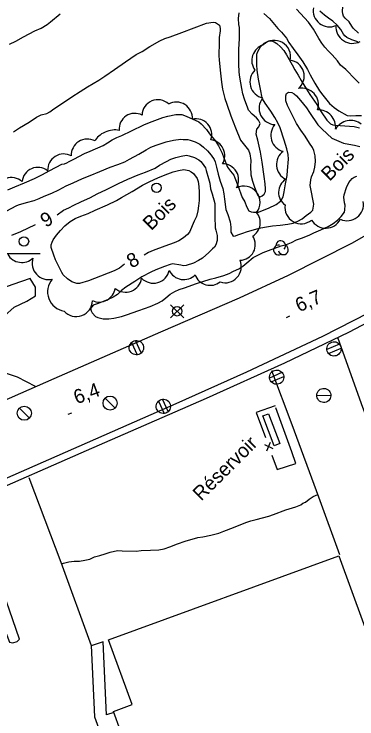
# Model space of a CAD drawing. Extents: x 381879 to 384696, y 5564785 to 5567594.
# Drawn here: x 384004.5 to 384077.4, y 5566301.1 to 5566450.9 of the extents above; entities that cross this region are included whole.
import ezdxf

# ---------------------------------------------------------------- set-up
doc = ezdxf.new("R2010")
doc.units = 0
for name, color, linetype in [('Niveau 19', 7, 'Continuous'), ('Niveau 2', 7, 'Continuous'), ('Niveau 21', 7, 'Continuous'), ('Niveau 22', 7, 'Continuous'), ('Niveau 3', 7, 'Continuous'), ('Niveau 31', 7, 'Continuous'), ('Niveau 33', 7, 'Continuous'), ('Niveau 36', 7, 'Continuous'), ('Niveau 37', 7, 'Continuous'), ('Niveau 4', 7, 'Continuous'), ('Niveau 44', 7, 'Continuous'), ('Niveau 52', 7, 'Continuous'), ('Niveau 61', 7, 'Continuous')]:
    doc.layers.add(name, color=color, linetype=linetype)

msp = doc.modelspace()

# ---------------------------------------------------------------- linework, layer by layer
at = {"layer": 'Niveau 19'}
msp.add_lwpolyline([(384009.04, 5566371.75), (384005.19, 5566373.71), (384000.87, 5566375.14), (383999.42, 5566377.48), (384000.4, 5566382.81), (384002.46, 5566386.78), (384004.5, 5566388.63), (384007.19, 5566389.9), (384009.07, 5566391.03), (384009.06, 5566392.88), (384007.91, 5566394.71), (384004.22, 5566393.43), (383997.83, 5566391.16), (383992.57, 5566388.92), (383990.33, 5566394.2), (383987.67, 5566392.42), (383990.65, 5566385.45), (383993.25, 5566376.84), (383995.32, 5566369.47), (383995.77, 5566367.6)], dxfattribs=at)
at = {"layer": 'Niveau 2'}
for points in [[(384077.69, 5566446.87), (384076.55, 5566447.9), (384076.29, 5566448.38), (384075.68, 5566449.28), (384074.86, 5566450.08), (384074.51, 5566450.51), (384074.33, 5566450.98), (384074.3, 5566451.49), (384074.35, 5566452.56), (384074.66, 5566453.64), (384075.1, 5566454.62), (384076.05, 5566456.52)], [(384077.87, 5566444.81), (384077.34, 5566445.08), (384076.25, 5566445.46), (384075.2, 5566445.94), (384074.8, 5566446.28), (384074.49, 5566446.68), (384073.92, 5566447.65), (384073.14, 5566448.55), (384072.25, 5566449.42), (384071.34, 5566450.05), (384070.44, 5566450.71), (384069.46, 5566451.52)], [(384003.17, 5566413.56), (384004.64, 5566414.2), (384006.7, 5566415.05), (384008.8, 5566415.96), (384010.4, 5566416.78), (384012.08, 5566417.71), (384014.67, 5566419.01), (384015.18, 5566419.09), (384015.67, 5566419.27), (384016.2, 5566419.61), (384017.21, 5566420.12), (384019.45, 5566421.26), (384020.67, 5566421.79), (384023.4, 5566423), (384024.37, 5566423.53), (384025.36, 5566424.16), (384026.33, 5566424.68), (384027.37, 5566425.14), (384029.45, 5566426.12), (384032.1, 5566427.41), (384033.28, 5566427.88), (384036.12, 5566428.95), (384037.19, 5566429.24), (384038.87, 5566429.57), (384040.11, 5566429.56), (384040.71, 5566429.4), (384041.73, 5566428.97), (384043.79, 5566428.01), (384044.24, 5566427.57), (384045.36, 5566426.4), (384046.04, 5566425.5), (384047.39, 5566423.82), (384047.93, 5566422.89), (384048.69, 5566421.34), (384049.05, 5566420.35), (384049.86, 5566418.41), (384050.5, 5566417.52), (384051.2, 5566416.71), (384051.43, 5566416.15), (384052.03, 5566414.51), (384052.96, 5566411.94), (384053.5, 5566410.99), (384053.91, 5566410.01), (384054.4, 5566409.1), (384054.87, 5566408.91), (384055.39, 5566408.84), (384056.41, 5566408.8), (384056.96, 5566409), (384058.54, 5566409.66), (384060.2, 5566410.47), (384061.12, 5566411.15), (384061.43, 5566411.56), (384061.67, 5566412.1), (384061.89, 5566413.15), (384062.2, 5566414.87), (384062.56, 5566416.59), (384062.62, 5566417.67), (384062.82, 5566420.05), (384062.75, 5566421.09), (384062.48, 5566422.25), (384061.91, 5566424.1), (384061.04, 5566426.75), (384060.54, 5566427.84), (384059.93, 5566428.97), (384059.09, 5566430.27), (384057.84, 5566431.97), (384057.29, 5566432.9), (384057.12, 5566433.47), (384056.92, 5566434.62), (384056.43, 5566437.12), (384056.18, 5566439), (384056.11, 5566440.14), (384056.11, 5566442.38), (384056.3, 5566442.94), (384056.83, 5566443.93), (384057.61, 5566444.71), (384058.65, 5566445.25), (384059.23, 5566445.21), (384059.77, 5566445.04)], [(384059.77, 5566445.04), (384060.31, 5566444.67), (384061.14, 5566443.98), (384061.85, 5566443.19), (384062.38, 5566442.23), (384063.6, 5566440.17), (384064.19, 5566439.04), (384064.87, 5566437.96), (384065.52, 5566436.79), (384066.61, 5566434.97), (384067.38, 5566433.84), (384068.82, 5566431.69), (384069.74, 5566430.15), (384070.93, 5566428.4), (384071.74, 5566427.6), (384072.22, 5566427.37), (384072.78, 5566427.28), (384073.81, 5566427.23), (384076.78, 5566427), (384077.88, 5566426.77)], [(384068.01, 5566409.24), (384068.2, 5566410.54), (384068.08, 5566411.23), (384067.63, 5566413.39), (384067.43, 5566414.5), (384067.54, 5566415.71), (384067.74, 5566416.32), (384068.18, 5566417.43), (384068.43, 5566418.4), (384068.56, 5566419.59), (384068.5, 5566420.78), (384068.23, 5566421.94), (384067.94, 5566422.53), (384067.25, 5566423.5), (384066.36, 5566424.96), (384065.45, 5566426.27), (384064.55, 5566427.69), (384063.98, 5566428.79), (384062.59, 5566431.47), (384062.24, 5566432.49), (384062.22, 5566433.53), (384062.39, 5566434.03), (384062.85, 5566434.34), (384063.49, 5566434.24), (384064.05, 5566433.97), (384064.5, 5566433.57), (384065.38, 5566432.59), (384066.66, 5566431.02), (384067.3, 5566430), (384069.07, 5566427.37), (384069.95, 5566426.49), (384072.05, 5566424.52), (384072.54, 5566424.31), (384074.54, 5566423.51), (384075.65, 5566423.25), (384076.87, 5566423.07), (384077.97, 5566422.76)], [(384002.95, 5566409.11), (384004.95, 5566410.15), (384005.44, 5566410.35), (384007.1, 5566410.87), (384008.76, 5566411.31), (384009.8, 5566411.7), (384010.9, 5566412.2), (384012.49, 5566412.84), (384014.01, 5566413.57), (384015.54, 5566414.4), (384017.05, 5566415.05), (384019.06, 5566415.97), (384020.64, 5566416.59), (384022.68, 5566417.46), (384024.92, 5566418.35), (384026.53, 5566418.93), (384028.02, 5566419.55), (384029, 5566420.06), (384031.01, 5566421.16), (384032.54, 5566422.1), (384033.59, 5566422.65), (384034.72, 5566423.05), (384036.84, 5566423.75), (384038.35, 5566424.12), (384039.9, 5566424.35), (384040.42, 5566424.26), (384041.44, 5566424.24), (384041.94, 5566424.12), (384042.95, 5566423.76), (384043.94, 5566423.27), (384044.75, 5566422.64), (384045.57, 5566421.83), (384046.36, 5566420.95), (384047.02, 5566420.03), (384047.2, 5566419.54), (384047.51, 5566418.39)], [(384013.62, 5566408.28), (384015.02, 5566409.26), (384016.13, 5566409.73), (384017.17, 5566410.3), (384018.69, 5566410.99), (384020.72, 5566411.96), (384022.17, 5566412.72), (384024.14, 5566413.65), (384026.68, 5566414.9), (384028.7, 5566415.83), (384030.87, 5566416.76), (384032.43, 5566417.34), (384034.45, 5566418.2), (384035.41, 5566418.8), (384036.85, 5566419.61), (384037.83, 5566420.05), (384038.88, 5566420.44), (384039.99, 5566420.74), (384041.17, 5566420.93), (384041.72, 5566420.82), (384042.81, 5566420.44), (384043.76, 5566419.95), (384044.16, 5566419.61), (384044.48, 5566419.2), (384045.15, 5566418.21), (384045.34, 5566417.66), (384045.84, 5566416), (384046.07, 5566414.95), (384046.23, 5566413.81), (384046.57, 5566412.73), (384047.16, 5566410.63), (384047.17, 5566409.54), (384047.13, 5566407.91), (384047.21, 5566405.5), (384047.4, 5566404.98), (384047.65, 5566403.84), (384047.67, 5566402.82), (384047.39, 5566401.84), (384047.09, 5566401.35), (384046.66, 5566401.01), (384045.85, 5566400.22)], [(384047.51, 5566418.39), (384047.84, 5566416.88), (384048.32, 5566415.43), (384048.89, 5566413.88), (384049.09, 5566412.75), (384049.22, 5566411.59), (384049.53, 5566409.35), (384049.91, 5566408.32), (384050.39, 5566406.78), (384050.54, 5566405.66), (384050.59, 5566404.6), (384051.07, 5566403.73), (384051.58, 5566403.82), (384052.06, 5566404.02), (384053.11, 5566404.36), (384053.87, 5566404.65)], [(384026.88, 5566396.92), (384025.79, 5566396.32), (384024.51, 5566395.86), (384022.83, 5566395.19), (384020.29, 5566394.2), (384018.4, 5566393.66), (384017.83, 5566393.68), (384016.77, 5566394.02), (384015.83, 5566394.64), (384014.94, 5566395.49), (384014.67, 5566396), (384013.31, 5566398.68), (384012.93, 5566399.65), (384012.38, 5566401.32), (384012.37, 5566401.87), (384012.55, 5566402.44), (384012.8, 5566402.91), (384013.5, 5566403.91), (384014.37, 5566404.92), (384015.3, 5566405.9), (384016.41, 5566406.83), (384017.48, 5566407.47), (384018.65, 5566407.95), (384020.22, 5566408.54), (384021.74, 5566409.23), (384024.31, 5566410.38), (384026.24, 5566411.3), (384027.3, 5566411.91), (384029.58, 5566413.24), (384031.77, 5566414.53), (384033.33, 5566415.32), (384035.05, 5566416.14), (384036.59, 5566416.78), (384038.33, 5566417.41), (384039.46, 5566417.69), (384040.58, 5566417.88), (384041.64, 5566417.69), (384042.14, 5566417.41), (384042.62, 5566417.01), (384043.43, 5566415.98), (384043.64, 5566415.37), (384043.79, 5566414.28), (384043.83, 5566413.06), (384043.81, 5566411.27), (384043.71, 5566410.14), (384043.54, 5566409.09), (384043.24, 5566407.93), (384042.8, 5566406.88), (384041.77, 5566404.6), (384041.36, 5566404.1), (384040.53, 5566403.38), (384039.54, 5566402.73), (384038.52, 5566402.32), (384036.52, 5566401.58), (384034.07, 5566400.7), (384033.05, 5566400.22), (384032.12, 5566399.68)], [(384021.12, 5566387.39), (384021.76, 5566386.62), (384022.28, 5566386.43), (384023.39, 5566386.17), (384024.66, 5566386.14), (384025.72, 5566386.3), (384027.29, 5566386.65), (384028.38, 5566387), (384031, 5566387.9), (384033.42, 5566388.78), (384035.02, 5566389.46), (384035.95, 5566389.97), (384036.77, 5566390.61), (384037.63, 5566391.37), (384038.63, 5566391.97), (384039.58, 5566392.37), (384040.68, 5566392.75), (384043.25, 5566393.63), (384046.18, 5566394.59), (384047.37, 5566394.86), (384049.09, 5566395.37), (384050.19, 5566395.77), (384051.16, 5566396.3), (384052.28, 5566396.77), (384053.14, 5566397.35), (384053.96, 5566398.06), (384055.29, 5566399.15), (384056.29, 5566399.71), (384057.4, 5566400.25), (384058.59, 5566400.69), (384061.26, 5566401.66), (384062.38, 5566401.97), (384063.48, 5566402.4), (384064.52, 5566402.91), (384065.55, 5566403.29), (384067.19, 5566403.96), (384068.21, 5566404.46), (384069.72, 5566405.09), (384071.23, 5566405.79), (384072.31, 5566406.4), (384073.21, 5566407.09), (384074, 5566407.9), (384074.69, 5566408.81), (384074.78, 5566409.32), (384074.88, 5566410.34), (384074.71, 5566410.82), (384074.55, 5566411.98), (384074.67, 5566412.48), (384075.15, 5566414.06), (384075.64, 5566415.1), (384076.35, 5566415.96), (384076.8, 5566416.24), (384077.36, 5566416.45)], [(384053.87, 5566404.65), (384056.61, 5566405.42), (384057.73, 5566405.63), (384059.38, 5566405.88), (384061.02, 5566406.05), (384062.69, 5566406.28), (384063.78, 5566406.51), (384064.78, 5566406.89), (384065.72, 5566407.4), (384066.58, 5566408.1), (384067.55, 5566408.79), (384067.92, 5566409.14), (384068.01, 5566409.24)], [(384004.01, 5566403.96), (384005.92, 5566404.72), (384009.01, 5566406.22)], [(384045.85, 5566400.22), (384044.55, 5566399.04), (384043.68, 5566398.53), (384042.62, 5566398.01), (384041.03, 5566397.45), (384040.5, 5566397.44), (384039.94, 5566397.57), (384038.18, 5566397.8), (384037.63, 5566397.7), (384036.43, 5566397.3), (384034.61, 5566396.59), (384033.58, 5566396.08), (384031.66, 5566395.05), (384030.13, 5566394.11), (384028.22, 5566392.89), (384027.35, 5566392.18), (384026.49, 5566391.34), (384025.52, 5566390.76), (384024.49, 5566390.26), (384022.39, 5566389.39), (384021.31, 5566389.03), (384020.74, 5566388.34), (384020.88, 5566387.85), (384021.12, 5566387.39)], [(384027.96, 5566397.75), (384026.88, 5566396.92)], [(384014.6, 5566334.05), (384015.02, 5566334.21), (384016.12, 5566334.49), (384017.25, 5566334.62), (384018.4, 5566334.66), (384019.5, 5566334.82), (384020.58, 5566335.07), (384021.6, 5566335.52), (384022.69, 5566335.87), (384023.87, 5566336.17), (384024.94, 5566336.55), (384026.46, 5566336.88), (384027.47, 5566336.85), (384030.42, 5566336.79), (384031.53, 5566336.89), (384033.46, 5566336.99), (384035.22, 5566337.01), (384036.4, 5566337.24), (384037.62, 5566337.67), (384039.2, 5566338.28), (384040.87, 5566338.85), (384043.53, 5566339.63), (384044.59, 5566339.81), (384046.33, 5566340.17), (384048, 5566340.6), (384049.09, 5566341), (384051.15, 5566341.8), (384053.74, 5566342.86), (384054.84, 5566343.23), (384055.95, 5566343.52), (384058.64, 5566344.22), (384059.64, 5566344.58), (384062.26, 5566345.53), (384064.35, 5566346.19), (384065.43, 5566346.58), (384065.89, 5566346.94), (384066.4, 5566347.2), (384067.22, 5566347.81), (384068.07, 5566348.39), (384069.04, 5566348.77)]]:
    msp.add_lwpolyline(points, dxfattribs=at)
at = {"layer": 'Niveau 21'}
for points in [[(383996.34, 5566366.17), (384012.98, 5566373.48), (384035.69, 5566383.38), (384052.41, 5566390.64), (384062.81, 5566395.4), (384076.43, 5566402.3), (384084.44, 5566406.91)], [(384086.25, 5566390.65), (384070.07, 5566382.36), (384053.88, 5566374.81), (384038.84, 5566368.1), (384020, 5566359.75), (383997.7, 5566349.98), (383974.77, 5566339.93), (383966.97, 5566336.23), (383957.74, 5566331.13), (383940.44, 5566321.75), (383930.51, 5566316.58), (383926.92, 5566314.19)]]:
    msp.add_lwpolyline(points, dxfattribs=at)
at = {"layer": 'Niveau 22'}
for points in [[(384104.77, 5566399.45), (384087.84, 5566389.69), (384075.56, 5566383.21), (384061.95, 5566376.75), (384045.29, 5566369.22), (384019.81, 5566358.09), (383997.16, 5566348.16), (383972.61, 5566337.32), (383961.6, 5566331.59), (383936.59, 5566317.95), (383927.52, 5566312.7), (383924.71, 5566310.02), (383921.91, 5566306.69), (383919.26, 5566302.33)], [(384025.66, 5566302.49), (384024.14, 5566301.95), (384023.44, 5566317.49), (384020.89, 5566316.65)]]:
    msp.add_lwpolyline(points, dxfattribs=at)
at = {"layer": 'Niveau 3'}
for p, q in [((384062.38, 5566386.43), (384063.1, 5566386.77)), ((384015.99, 5566365.88), (384016.73, 5566366.18))]:
    msp.add_line(p, q, dxfattribs=at)
at = {"layer": 'Niveau 31'}
msp.add_lwpolyline([(384098.59, 5566266.93), (384097.57, 5566266.61), (384098.32, 5566264.57), (384050.54, 5566247.37), (384049.87, 5566249.19), (384047.71, 5566255.13), (384041.78, 5566252.97), (384036.51, 5566267.44), (384038.41, 5566268.13), (384029.8, 5566291.77), (384026.75, 5566290.66), (384024.26, 5566297.5), (384027.1, 5566298.53), (384025.59, 5566302.68), (384029.57, 5566304.13), (384024.56, 5566317.89), (384073.53, 5566335.73)], close=True, dxfattribs=at)
at = {"layer": 'Niveau 33'}
msp.add_lwpolyline([(384058.57, 5566365.93), (384060.98, 5566359.64), (384059.76, 5566359.17), (384057.39, 5566365.52)], close=True, dxfattribs=at)
at = {"layer": 'Niveau 36'}
for p, q in [((384040.56, 5566389.15), (384037.74, 5566386.33)), ((384040.56, 5566386.33), (384037.74, 5566389.15)), ((384029.47, 5566381.13), (384030.68, 5566378.5)), ((384031.51, 5566378.91), (384030.3, 5566381.54)), ((384073.64, 5566380.73), (384070.97, 5566379.61)), ((384071.34, 5566378.77), (384074.01, 5566379.89)), ((384061.42, 5566374.75), (384058.77, 5566373.56)), ((384059.16, 5566372.73), (384061.81, 5566373.92)), ((384025.96, 5566367.17), (384023.84, 5566369.29)), ((384037.23, 5566366.41), (384036.04, 5566369.05)), ((384068.81, 5566369.82), (384071.81, 5566369.92)), ((384035.21, 5566368.65), (384036.4, 5566366.01)), ((384007.73, 5566365.03), (384005.61, 5566367.15))]:
    msp.add_line(p, q, dxfattribs=at)
for centre, radius in [((384034.78, 5566414), 1), ((384006.59, 5566402.6), 1), ((384039.14, 5566387.74), 1), ((384024.89, 5566368.23), 1.5), ((384006.66, 5566366.09), 1.5)]:
    msp.add_circle(centre, radius, dxfattribs=at)
for centre, major_axis, ratio in [((384030.49, 5566380.01), (1.22, -0.91), 0.999873), ((384072.48, 5566379.75), (1.21, -0.92), 0.999876), ((384060.3, 5566373.74), (-1.21, 0.92), 0.999874), ((384070.32, 5566369.87), (1.2, -0.9), 0.999875), ((384036.22, 5566367.54), (1.21, -0.91), 0.999875)]:
    msp.add_ellipse(centre, major_axis=major_axis, ratio=ratio, dxfattribs=at)
at = {"layer": 'Niveau 37'}
for p, q in [((384058.19, 5566358.11), (384059.02, 5566359.93)), ((384057.69, 5566359.43), (384059.51, 5566358.6))]:
    msp.add_line(p, q, dxfattribs=at)
for points in [[(384059.98, 5566367.68), (384055.92, 5566366.22), (384057.91, 5566360.89)], [(384063.51, 5566357.85), (384060.13, 5566367.26)], [(384059.3, 5566357.14), (384060.43, 5566354.12), (384064.39, 5566355.39), (384063.51, 5566357.85)]]:
    msp.add_lwpolyline(points, dxfattribs=at)
at = {"layer": 'Niveau 4'}
for points in [[(384049.69, 5566431.81), (384050.59, 5566429.33), (384051.53, 5566426.77), (384052.58, 5566424.12), (384052.91, 5566423.74), (384054.34, 5566422.02), (384054.62, 5566421.24), (384054.79, 5566419.81), (384054.72, 5566418.5), (384054.83, 5566416.77), (384055.14, 5566415.39), (384055.59, 5566414.14), (384056.32, 5566412.36), (384056.76, 5566412.06), (384057.24, 5566412.28), (384057.62, 5566412.63), (384057.93, 5566413.2), (384057.96, 5566413.79), (384057.88, 5566414.83), (384057.64, 5566416.41), (384057.22, 5566419.43), (384056.86, 5566421.59), (384056.31, 5566424.11), (384055.91, 5566425.42), (384056.06, 5566426.46), (384056.54, 5566426.98), (384056.77, 5566427.65), (384056.47, 5566428.37), (384056.01, 5566428.86), (384055.07, 5566429.65), (384054.33, 5566430.47), (384054.14, 5566430.95), (384053.46, 5566432.83), (384053.14, 5566433.94), (384052.92, 5566435.13), (384052.44, 5566437.5), (384052.31, 5566438.58), (384052.23, 5566440.37), (384052.28, 5566441.52), (384052.28, 5566443.5), (384052.4, 5566445.63), (384052.39, 5566448.07), (384052.25, 5566448.71), (384052.18, 5566450.02), (384052.34, 5566451.17)], [(384071.29, 5566443.02), (384070.53, 5566443.88), (384069.88, 5566444.75), (384069.29, 5566445.72), (384068.14, 5566447.71), (384067.09, 5566449.22), (384066.23, 5566450.15), (384064.52, 5566451.94)], [(384003.53, 5566444.52), (384004.84, 5566445.19), (384006.51, 5566446.1), (384008.9, 5566447.37), (384010.21, 5566447.93), (384011.55, 5566448.74), (384012.22, 5566449.3), (384014.25, 5566450.98)], [(384057.58, 5566451.05), (384058.75, 5566449.96), (384059.47, 5566449.17), (384060.56, 5566447.88), (384061.33, 5566447.09), (384062.36, 5566445.8), (384062.92, 5566444.92), (384063.81, 5566443.63), (384064.83, 5566442.27), (384065.86, 5566440.77), (384066.85, 5566439.14), (384067.45, 5566437.98), (384068.43, 5566436.26), (384069.43, 5566434.59), (384070.11, 5566433.69), (384071.53, 5566431.93), (384072.52, 5566431.1), (384073.49, 5566430.38), (384075.32, 5566429.34), (384075.9, 5566429.27), (384077.15, 5566429.34), (384078.34, 5566429.34)], [(384004.39, 5566425.88), (384005.67, 5566426.72), (384007.69, 5566427.97), (384009.24, 5566429), (384010.26, 5566429.48), (384011.44, 5566429.77), (384012.09, 5566430.13), (384012.97, 5566430.8), (384014.54, 5566431.86), (384016.76, 5566433.36), (384018.52, 5566434.5), (384020.11, 5566435.43), (384022.51, 5566436.88), (384023.75, 5566437.72), (384025.83, 5566439.13), (384028.19, 5566440.79), (384030.47, 5566442.32), (384031.69, 5566443), (384033.31, 5566444), (384035.46, 5566445.27), (384036.56, 5566445.73), (384037.69, 5566446.12), (384040.12, 5566447), (384042.75, 5566447.97), (384045.4, 5566448.98), (384046.77, 5566449.22), (384047.31, 5566449.15), (384048.12, 5566448.59), (384048.29, 5566447.87), (384048.26, 5566447.34), (384048.06, 5566445.94), (384048.05, 5566444.82), (384048, 5566442.14), (384048.08, 5566441.14), (384048.34, 5566438.34), (384048.57, 5566436.43), (384048.82, 5566434.99), (384049.26, 5566433), (384049.69, 5566431.81)], [(384077.81, 5566436.24), (384077.09, 5566437.01), (384074.97, 5566439.13), (384073.9, 5566440.05), (384073.22, 5566440.96), (384072.08, 5566442.26), (384071.29, 5566443.02)]]:
    msp.add_lwpolyline(points, dxfattribs=at)
at = {"layer": 'Niveau 44'}
for centre, radius, start, end in [((384069.17, 5566426.88), 3.68, 353.5308, 92.5777), ((384076.01, 5566424.66), 3.66, 51.6098, 150.5444), ((384020.05, 5566420.96), 3.41, 61.3039, 183.1961), ((384015.02, 5566417.79), 3.4, 61.2552, 182.8579)]:
    msp.add_arc(centre, radius, start, end, dxfattribs=at)
for centre, major_axis, ratio, start_param, end_param in [((384071.55, 5566451.71), (-1.15, -3.31), 0.997968, 4.887249, 7.012758), ((384076.42, 5566448.24), (-2.15, -2.81), 0.999301, 5.295818, 7.418747), ((384059.8, 5566441.88), (-2.56, 2.31), 0.999985, 3.646936, 6.195676), ((384058.46, 5566441.06), (-1.49, -3.13), 0.99196, 3.878085, 5.788299), ((384062.71, 5566437.7), (2.83, 1.99), 0.984542, 4.798942, 7.120529), ((384058.15, 5566436.51), (-3.39, -0.95), 0.99881, 5.21609, 7.34179), ((384065.69, 5566431.68), (2.6, 2.34), 0.999995, 5.221913, 7.346673), ((384035.03, 5566429.38), (-3.16, -1.07), 0.999742, 3.632588, 5.937853), ((384038.95, 5566428.78), (1.85, 2.91), 0.999862, 5.219223, 7.346613), ((384060.07, 5566430.92), (-3.23, -1.34), 0.999952, 5.222425, 7.418277), ((384030.15, 5566426.47), (-3.06, -1.36), 0.99974, 3.812492, 5.945345), ((384043.15, 5566425.3), (2.49, 2.26), 0.999792, 5.218985, 7.344549), ((384062.55, 5566425.13), (-3.38, -0.88), 0.999464, 5.30844, 7.346388), ((384024.79, 5566424.15), (-3.16, -1.19), 0.56753, 3.824811, 5.788865), ((384045.84, 5566420.87), (3.43, -0.1), 0.985899, 5.761898, 7.738875), ((384063.72, 5566418.95), (0.47, -3.43), 0.997437, 3.636905, 5.690822), ((384009.54, 5566414.95), (-1.33, 3.11), 0.999179, 5.215923, 7.345476), ((384048.79, 5566415.68), (-1.2, 3.21), 0.997803, 3.838534, 5.930972), ((384003.91, 5566412.76), (-1.14, 3.21), 0.999994, 5.217876, 7.345643), ((384064.14, 5566413.12), (-3.1, -1.53), 0.966841, 4.86642, 6.775301), ((384053.38, 5566410.96), (-2.68, 2.14), 0.990292, 3.112583, 5.872187), ((384075.31, 5566410.44), (2.77, 2.08), 0.991266, 3.636005, 5.81894), ((384065.52, 5566409.81), (3.46, -0.18), 0.998236, 3.035945, 5.449372), ((384053.39, 5566406.57), (3.43, 0), 0.974199, 5.272711, 6.991392), ((384070.72, 5566409.19), (0.09, -3.78), 0.951775, 5.265834, 7.308919), ((384052.11, 5566402.08), (3.27, -1.73), 0.931278, 5.277179, 7.291883), ((384060.68, 5566400.79), (-0.836, 0.629), 0.999875, 5.163765, 9.050341), ((384061.17, 5566401.71), (-0.836, 0.629), 0.999875, 3.020126, 6.959135), ((384061.73, 5566400.83), (-0.836, 0.629), 0.999875, 0.893509, 4.863384), ((384006.11, 5566401.52), (3.27, -1.05), 0.985062, 3.977022, 5.787854), ((384011.8, 5566397.97), (-2.57, -2.36), 0.998943, 5.222011, 7.347586), ((384049.36, 5566397.25), (0.32, 3.43), 0.990945, 2.919994, 5.199469), ((384034.1, 5566397.16), (0.86, -3.34), 0.99995, 5.221806, 7.393889), ((384040.57, 5566397.94), (-1.46, -3.13), 0.999765, 5.597094, 7.498714), ((384015.76, 5566391.89), (-3.89, -1.47), 0.996101, 5.215504, 7.336606), ((384028.18, 5566395.28), (1.25, -3.23), 0.996569, 5.220189, 7.340046), ((384046.21, 5566396.65), (3.24, 1.13), 0.984565, 3.150768, 5.04145), ((384022.59, 5566393.09), (3.22, 1.18), 0.986124, 3.92691, 5.789972), ((384017.72, 5566390), (3.35, 0.73), 0.985148, 3.634205, 6.064023)]:
    msp.add_ellipse(centre, major_axis=major_axis, ratio=ratio, start_param=start_param, end_param=end_param, dxfattribs=at)
at = {"layer": 'Niveau 52'}
for points in [[(384078.58, 5566162.62), (384077.1, 5566162.45), (384075.97, 5566163.26), (384075.09, 5566165.99), (384074.12, 5566169.6), (384074.45, 5566171.63), (384075.15, 5566173.4), (384078.34, 5566175.39), (384084.85, 5566177.94), (384087.45, 5566179.7), (384099.08, 5566191.62), (384114.02, 5566207.23), (384131.85, 5566225.7), (384132.92, 5566228.4), (384133.06, 5566230.88), (384119.64, 5566265.01), (384113.12, 5566273.05), (384101.68, 5566304.51), (384087.96, 5566342.21), (384078.31, 5566368.08), (384073.32, 5566382.15)], [(384073.74, 5566335.97), (384069.24, 5566348.22), (384063.62, 5566363.58), (384059.29, 5566375.12)], [(384007.62, 5566352.38), (384014.46, 5566334.42), (384020.89, 5566316.7)], [(383933.09, 5566298.9), (383933.64, 5566301.67), (383934.15, 5566303.6), (383935.06, 5566306.02), (383936.09, 5566308.41), (383937.31, 5566310.29), (383938.88, 5566312.58), (383940.17, 5566314.32), (383941.97, 5566316.23), (383944.05, 5566317.67), (383963.94, 5566328.95), (383994.74, 5566340.22), (384003.5, 5566317.39), (384004.25, 5566317.3), (384005.14, 5566317.53), (384005.67, 5566318.07), (384000.65, 5566332.24)], [(384020.89, 5566316.7), (384021.61, 5566301.53), (384039.36, 5566252.64)]]:
    msp.add_lwpolyline(points, dxfattribs=at)
at = {"layer": 'Niveau 61'}
msp.add_lwpolyline([(383990, 5566400), (384000, 5566400), (384010, 5566400)], dxfattribs=at)

# ---------------------------------------------------------------- texts
at = {"layer": 'Niveau 2'}
for s, rotation, p in [('6', 210.2483, (384011.61, 5566409.18)), ('8', 28.5374, (384029.45, 5566396.81))]:
    msp.add_text(s, height=3, rotation=rotation, dxfattribs=at).set_placement(p)
at = {"layer": 'Niveau 3'}
for s, rotation, p in [('6,7  ', 23.1932, (384065.05, 5566387.51)), ('6,4  ', 20.0122, (384017.79, 5566367.95))]:
    msp.add_text(s, height=3, rotation=rotation, dxfattribs=at).set_placement(p)
at = {"layer": 'Niveau 33'}
msp.add_text('Réservoir', height=3, rotation=44.7717, dxfattribs=at).set_placement((384044.26, 5566347.29))
at = {"layer": 'Niveau 44'}
for p in [(384071.53, 5566415.26), (384033.64, 5566404.77)]:
    msp.add_text('Bois', height=3, rotation=44.7707, dxfattribs=at).set_placement(p)

doc.saveas('drawing.dxf')
